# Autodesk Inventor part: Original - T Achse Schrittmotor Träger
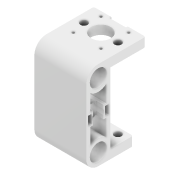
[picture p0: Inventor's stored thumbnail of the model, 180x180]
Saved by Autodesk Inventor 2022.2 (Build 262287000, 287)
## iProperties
Created: 2024-09
Part Number: Original - T Achse Schrittmotor Träger
Material: Plastica ABS
Document SubType Name: Modeling
Designer: 18907419
Density: 1.06 g/cm^3
Appearance: Liscia - Bianco
Author: 18907419
Revision Number: ANY
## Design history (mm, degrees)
feature "Schnitt-Linear austragen9"
node "Solido1"
